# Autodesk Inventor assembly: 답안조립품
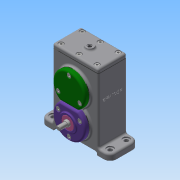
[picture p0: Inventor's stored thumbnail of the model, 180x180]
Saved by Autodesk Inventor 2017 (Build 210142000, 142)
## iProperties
Part Number: 답안조립품
Material: 일반
Document SubType Name: Assembly
Designer: 222
Mass: 1084.23 g
Surface Area: 1575.48 cm^2
Volume: 385.032 cm^3
Density: 2.81594 g/cm^3
Author: 222
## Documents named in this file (24)
- C:\Users\222\Desktop\600506V1020\답안조립품.iam
- C:\Users\222\Desktop\600506V1020\본체.ipt
- C:\Users\222\Desktop\600506V1020\Ű 4 x 4 x 12.ipt
- C:\Users\222\Desktop\600506V1020\Ű 5 x 5 x 12.ipt
- C:\Users\222\Desktop\600506V1020\개스킷 A.ipt
- C:\Users\222\Desktop\600506V1020\개스킷 B.ipt
- C:\Users\222\Desktop\600506V1020\개스킷 C.ipt
- C:\Users\222\Desktop\600506V1020\베어링 6001.ipt
- 베어링 6001.ipt
- C:\Users\222\Desktop\600506V1020\베어링 6002.ipt
- 베어링 6002.ipt
- C:\Users\222\Desktop\600506V1020\볼트 M4.ipt
- C:\Users\222\Desktop\600506V1020\스퍼기어 A.ipt
- C:\Users\222\Desktop\600506V1020\스퍼기어 B.ipt
- C:\Users\222\Desktop\600506V1020\오일 실 10 20 7.ipt
- C:\Users\222\Desktop\600506V1020\오일 실 12 22 7.ipt
- C:\Users\222\Desktop\600506V1020\축 A.ipt
- C:\Users\222\Desktop\600506V1020\축 B.ipt
- C:\Users\222\Desktop\600506V1020\칼라.ipt
- C:\Users\222\Desktop\600506V1020\커버 A.ipt
- C:\Users\222\Desktop\600506V1020\커버 B.ipt
- C:\Users\222\Desktop\600506V1020\커버 C.ipt
- C:\Users\222\Desktop\600506V1020\커버 D.ipt
- C:\Users\222\Desktop\600506V1020\커버 E.ipt
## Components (7 placed, 5 different names)
1. Ű 4 x 4 x 12:1
2. 개스킷 A:1
3. 개스킷 B:1
4. 개스킷 C:1
5. 개스킷 B:2
6. 개스킷 B:3
7. Ű 5 x 5 x 12:1
